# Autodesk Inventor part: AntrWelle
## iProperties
Shininess: 64.0
Length Units: 11269
Angle Units: 11279
Time Units: 11290
Mass Units: 11283
Length Display Precision: 3
Angle Display Precision: 2
Compacted: True
Part Number: AntrWelle
Document SubType Name: Modeling
Created: 2004-01
Material: Standard
Designer: chefe
Manufacturer: Standard
Standards Organization: Custom
Density: 0.0
Volumn: 0.0
Area: 0.0
PropertySet Name: Model Information
Control State: 0
Master: False
Checked Out: False
Author: chefe
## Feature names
1. Extrusion1
2. Extrusion2
